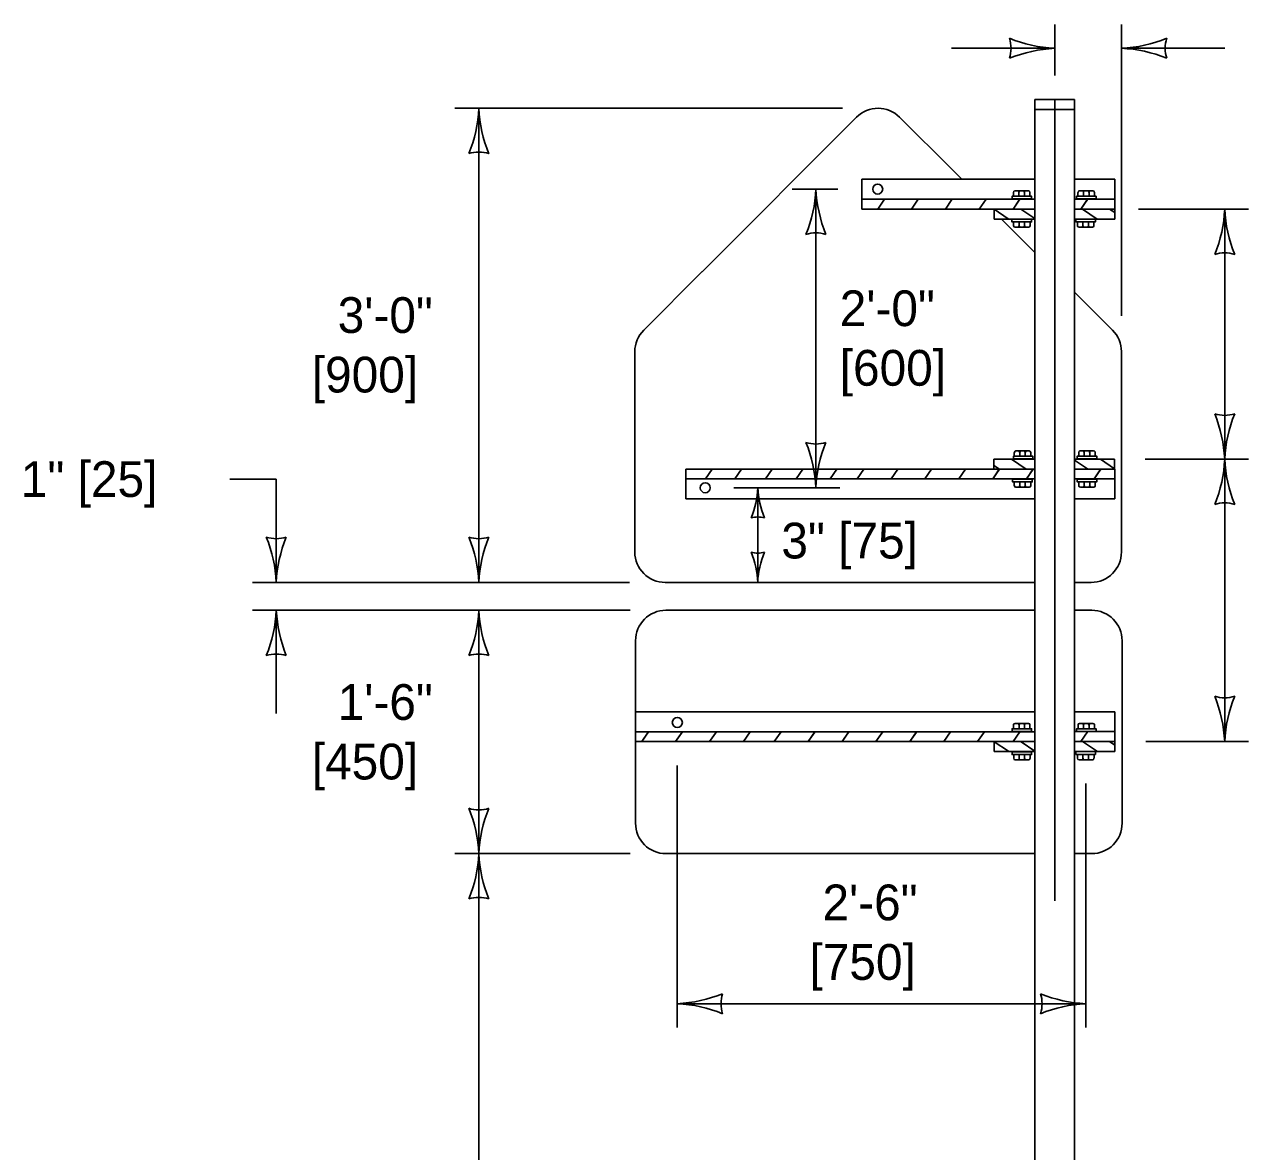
# Model space of a CAD drawing. Extents: x 49991.4 to 50021, y 49987.6 to 50011.4.
# Drawn here: x 50005.155 to 50007.21, y 49995.939 to 49997.831 of the extents above; entities that cross this region are included whole.
import ezdxf

# ---------------------------------------------------------------- set-up
doc = ezdxf.new("R2010")
doc.units = 0
for name, color, linetype in [('Level 1', 7, 'Continuous'), ('Level 2', 7, 'Continuous'), ('Level 3', 7, 'Continuous'), ('Level 4', 7, 'Continuous')]:
    doc.layers.add(name, color=color, linetype=linetype)

msp = doc.modelspace()

# ---------------------------------------------------------------- linework, layer by layer
at = {"layer": 'Level 1'}
for p, q in [((50006.8517, 49997.7052), (50006.9182, 49997.7052)), ((50006.8517, 49997.7052), (50006.8517, 49997.0109)), ((50006.9182, 49997.7052), (50006.9182, 49997.0137)), ((50006.2929, 49997.416), (50006.5522, 49997.6753)), ((50006.6244, 49997.6753), (50006.713, 49997.5868)), ((50006.8517, 49997.6885), (50006.9182, 49997.6885)), ((50006.5609, 49997.5711), (50006.5609, 49997.5211)), ((50006.5609, 49997.5711), (50006.8506, 49997.5711)), ((50006.713, 49997.5868), (50006.7287, 49997.5711)), ((50006.918, 49997.5711), (50006.9857, 49997.5711)), ((50006.9857, 49997.5711), (50006.9857, 49997.5044)), ((50006.8156, 49997.5491), (50006.8156, 49997.5429)), ((50006.8407, 49997.5516), (50006.818, 49997.5516)), ((50006.8408, 49997.5516), (50006.818, 49997.5516)), ((50006.8248, 49997.5516), (50006.8248, 49997.5429)), ((50006.8341, 49997.5516), (50006.8341, 49997.5429)), ((50006.8432, 49997.5491), (50006.8432, 49997.5429)), ((50006.9239, 49997.5491), (50006.9239, 49997.5429)), ((50006.949, 49997.5516), (50006.9264, 49997.5516)), ((50006.9491, 49997.5516), (50006.9264, 49997.5516)), ((50006.9331, 49997.5516), (50006.9331, 49997.5429)), ((50006.9424, 49997.5516), (50006.9424, 49997.5429)), ((50006.9515, 49997.5491), (50006.9515, 49997.5429)), ((50006.5609, 49997.5379), (50006.8512, 49997.5379)), ((50006.5876, 49997.5211), (50006.5989, 49997.5379)), ((50006.6444, 49997.5211), (50006.6557, 49997.5379)), ((50006.7013, 49997.5211), (50006.7122, 49997.5373)), ((50006.7582, 49997.5211), (50006.7695, 49997.5379)), ((50006.815, 49997.5211), (50006.8263, 49997.5379)), ((50006.815, 49997.5211), (50006.8259, 49997.5373)), ((50006.815, 49997.5211), (50006.8259, 49997.5373)), ((50006.815, 49997.5211), (50006.8259, 49997.5373)), ((50006.918, 49997.5379), (50006.9857, 49997.5379)), ((50006.918, 49997.5379), (50006.9857, 49997.5379)), ((50006.9288, 49997.5211), (50006.9401, 49997.5379)), ((50006.9288, 49997.5211), (50006.9397, 49997.5373)), ((50006.5609, 49997.5211), (50006.7831, 49997.5211)), ((50006.7831, 49997.5044), (50006.7831, 49997.5211)), ((50006.7831, 49997.5211), (50006.8512, 49997.5211)), ((50006.8069, 49997.5048), (50006.7831, 49997.5209)), ((50006.8517, 49997.5052), (50006.8281, 49997.5211)), ((50006.918, 49997.5211), (50006.9857, 49997.5211)), ((50006.918, 49997.5211), (50006.9857, 49997.5211)), ((50006.918, 49997.5211), (50006.9857, 49997.5211)), ((50006.9562, 49997.5044), (50006.9315, 49997.5211)), ((50006.9857, 49997.5151), (50006.9767, 49997.5211)), ((50006.7831, 49997.5044), (50006.8517, 49997.5044)), ((50006.7953, 49997.5044), (50006.8517, 49997.4482)), ((50006.8158, 49997.4931), (50006.8158, 49997.4993)), ((50006.8182, 49997.4905), (50006.8409, 49997.4905)), ((50006.8183, 49997.4905), (50006.8409, 49997.4905)), ((50006.8249, 49997.4905), (50006.8249, 49997.4993)), ((50006.8342, 49997.4905), (50006.8342, 49997.4993)), ((50006.8434, 49997.4931), (50006.8434, 49997.4993)), ((50006.9183, 49997.5044), (50006.9857, 49997.5044)), ((50006.923, 49997.4932), (50006.923, 49997.4994)), ((50006.9255, 49997.4906), (50006.9482, 49997.4906)), ((50006.9256, 49997.4906), (50006.9482, 49997.4906)), ((50006.9321, 49997.4906), (50006.9321, 49997.4994)), ((50006.9415, 49997.4906), (50006.9415, 49997.4994)), ((50006.9507, 49997.4932), (50006.9507, 49997.4994)), ((50006.1948, 49997.3179), (50006.2927, 49997.4162)), ((50006.9182, 49997.3815), (50006.932, 49997.3677)), ((50006.932, 49997.3677), (50006.9819, 49997.3179)), ((50006.1798, 49996.9455), (50006.1798, 49997.2818)), ((50006.9968, 49997.2818), (50006.9968, 49996.9455)), ((50006.7828, 49997.1014), (50006.7828, 49997.0847)), ((50006.8517, 49997.1014), (50006.7828, 49997.1014)), ((50006.8124, 49997.1014), (50006.8371, 49997.0847)), ((50006.817, 49997.1126), (50006.817, 49997.1063)), ((50006.8196, 49997.1152), (50006.842, 49997.1152)), ((50006.8196, 49997.1152), (50006.842, 49997.1152)), ((50006.8261, 49997.1152), (50006.8261, 49997.1063)), ((50006.8354, 49997.1152), (50006.8354, 49997.1063)), ((50006.8446, 49997.1126), (50006.8446, 49997.1063)), ((50006.9854, 49997.1014), (50006.9182, 49997.1014)), ((50006.9182, 49997.0998), (50006.9401, 49997.0849)), ((50006.9251, 49997.1127), (50006.9251, 49997.1064)), ((50006.9277, 49997.1153), (50006.9501, 49997.1153)), ((50006.9277, 49997.1153), (50006.9501, 49997.1153)), ((50006.9342, 49997.1153), (50006.9342, 49997.1064)), ((50006.9435, 49997.1153), (50006.9435, 49997.1064)), ((50006.9527, 49997.1127), (50006.9527, 49997.1064)), ((50006.9616, 49997.1011), (50006.9854, 49997.085)), ((50006.9854, 49997.1014), (50006.9854, 49997.085)), ((50006.2655, 49997.0847), (50006.2655, 49997.0347)), ((50006.7828, 49997.0847), (50006.2655, 49997.0847)), ((50006.2985, 49997.068), (50006.3098, 49997.0847)), ((50006.3477, 49997.068), (50006.359, 49997.0847)), ((50006.3993, 49997.068), (50006.4106, 49997.0847)), ((50006.4505, 49997.068), (50006.4619, 49997.0847)), ((50006.5076, 49997.068), (50006.5189, 49997.0847)), ((50006.553, 49997.068), (50006.5642, 49997.0846)), ((50006.61, 49997.068), (50006.6213, 49997.0847)), ((50006.6669, 49997.068), (50006.6781, 49997.0847)), ((50006.7236, 49997.068), (50006.7349, 49997.0847)), ((50006.7807, 49997.068), (50006.7919, 49997.0847)), ((50006.7812, 49997.0687), (50006.7905, 49997.0826)), ((50006.7828, 49997.0908), (50006.7919, 49997.0847)), ((50006.8505, 49997.0847), (50006.7828, 49997.0847)), ((50006.8517, 49997.0847), (50006.7828, 49997.0847)), ((50006.8375, 49997.068), (50006.8487, 49997.0847)), ((50006.838, 49997.0688), (50006.8477, 49997.0832)), ((50006.9857, 49997.0847), (50006.9174, 49997.0847)), ((50006.9857, 49997.0847), (50006.9174, 49997.0847)), ((50006.9857, 49997.0847), (50006.9182, 49997.0847)), ((50006.9513, 49997.0682), (50006.9624, 49997.0847)), ((50006.9513, 49997.0682), (50006.9614, 49997.0832)), ((50006.9857, 49997.0847), (50006.9857, 49997.0347)), ((50006.8517, 49997.068), (50006.2655, 49997.068)), ((50006.817, 49997.0568), (50006.817, 49997.0631)), ((50006.8261, 49997.0542), (50006.8261, 49997.0631)), ((50006.8354, 49997.0542), (50006.8354, 49997.0631)), ((50006.8446, 49997.0568), (50006.8446, 49997.0631)), ((50006.9857, 49997.068), (50006.9174, 49997.068)), ((50006.9857, 49997.068), (50006.9182, 49997.068)), ((50006.9253, 49997.0568), (50006.9253, 49997.0631)), ((50006.9344, 49997.0542), (50006.9344, 49997.0631)), ((50006.9437, 49997.0542), (50006.9437, 49997.0631)), ((50006.9529, 49997.0568), (50006.9529, 49997.0631)), ((50006.8517, 49997.0347), (50006.2655, 49997.0347)), ((50006.8196, 49997.0542), (50006.842, 49997.0542)), ((50006.8196, 49997.0542), (50006.842, 49997.0542)), ((50006.9857, 49997.0347), (50006.9182, 49997.0347)), ((50006.9279, 49997.0542), (50006.9503, 49997.0542)), ((50006.9279, 49997.0542), (50006.9503, 49997.0542)), ((50006.9182, 49997.0137), (50006.9182, 49994.5439)), ((50006.8517, 49997.0109), (50006.8517, 49994.5439)), ((50006.8517, 49996.8944), (50006.2309, 49996.8944)), ((50006.9458, 49996.8944), (50006.9182, 49996.8944)), ((50006.2321, 49996.8476), (50006.8517, 49996.8476)), ((50006.9182, 49996.8476), (50006.9469, 49996.8476)), ((50006.181, 49996.4902), (50006.181, 49996.7965)), ((50006.998, 49996.7965), (50006.998, 49996.4902)), ((50006.1815, 49996.6771), (50006.8513, 49996.6771)), ((50006.9188, 49996.6772), (50006.9858, 49996.6772)), ((50006.9858, 49996.6772), (50006.9858, 49996.6105)), ((50006.181, 49996.6438), (50006.851, 49996.6438)), ((50006.1915, 49996.6271), (50006.2028, 49996.6438)), ((50006.2484, 49996.6271), (50006.2598, 49996.6438)), ((50006.3053, 49996.6271), (50006.3167, 49996.6438)), ((50006.3621, 49996.6271), (50006.3735, 49996.6438)), ((50006.414, 49996.6271), (50006.4253, 49996.6438)), ((50006.4709, 49996.6271), (50006.4822, 49996.6438)), ((50006.5278, 49996.6271), (50006.5392, 49996.6438)), ((50006.5846, 49996.6271), (50006.596, 49996.6438)), ((50006.6415, 49996.6271), (50006.6529, 49996.6438)), ((50006.6984, 49996.6271), (50006.7098, 49996.6438)), ((50006.7554, 49996.6271), (50006.7667, 49996.6438)), ((50006.8151, 49996.6272), (50006.8263, 49996.6438)), ((50006.8157, 49996.6551), (50006.8157, 49996.6489)), ((50006.8408, 49996.6577), (50006.8181, 49996.6577)), ((50006.8408, 49996.6577), (50006.8181, 49996.6577)), ((50006.8249, 49996.6577), (50006.8249, 49996.6489)), ((50006.8342, 49996.6577), (50006.8342, 49996.6489)), ((50006.8433, 49996.6551), (50006.8433, 49996.6489)), ((50006.9181, 49996.6439), (50006.9858, 49996.6439)), ((50006.9182, 49996.6439), (50006.9858, 49996.6439)), ((50006.924, 49996.6551), (50006.924, 49996.6489)), ((50006.9491, 49996.6577), (50006.9264, 49996.6577)), ((50006.9492, 49996.6577), (50006.9264, 49996.6577)), ((50006.9332, 49996.6577), (50006.9332, 49996.6489)), ((50006.9425, 49996.6577), (50006.9425, 49996.6489)), ((50006.9516, 49996.6551), (50006.9516, 49996.6489)), ((50006.181, 49996.6271), (50006.7832, 49996.6271)), ((50006.1915, 49996.6271), (50006.2024, 49996.6432)), ((50006.1915, 49996.6271), (50006.2024, 49996.6432)), ((50006.2484, 49996.6271), (50006.2594, 49996.6432)), ((50006.2484, 49996.6271), (50006.2594, 49996.6432)), ((50006.4709, 49996.6271), (50006.4818, 49996.6432)), ((50006.4709, 49996.6271), (50006.4818, 49996.6432)), ((50006.5277, 49996.6271), (50006.5387, 49996.6432)), ((50006.5278, 49996.6271), (50006.5388, 49996.6432)), ((50006.5278, 49996.6271), (50006.5388, 49996.6432)), ((50006.5846, 49996.6271), (50006.5956, 49996.6432)), ((50006.5846, 49996.6271), (50006.5956, 49996.6432)), ((50006.5847, 49996.6271), (50006.5957, 49996.6432)), ((50006.6415, 49996.6271), (50006.6525, 49996.6432)), ((50006.7832, 49996.6105), (50006.7832, 49996.6271)), ((50006.7832, 49996.6271), (50006.8517, 49996.6271)), ((50006.807, 49996.6109), (50006.7832, 49996.6269)), ((50006.8151, 49996.6272), (50006.826, 49996.6433)), ((50006.8151, 49996.6272), (50006.826, 49996.6433)), ((50006.8151, 49996.6272), (50006.826, 49996.6433)), ((50006.8517, 49996.6112), (50006.8285, 49996.627)), ((50006.9181, 49996.6272), (50006.9858, 49996.6272)), ((50006.9181, 49996.6272), (50006.9858, 49996.6272)), ((50006.9182, 49996.6272), (50006.9858, 49996.6272)), ((50006.9289, 49996.6272), (50006.9398, 49996.6433)), ((50006.9289, 49996.6272), (50006.9398, 49996.6433)), ((50006.9564, 49996.6104), (50006.9317, 49996.6272)), ((50006.9858, 49996.6211), (50006.9767, 49996.6272)), ((50006.7832, 49996.6105), (50006.8517, 49996.6105)), ((50006.8159, 49996.5992), (50006.8159, 49996.6055)), ((50006.825, 49996.5966), (50006.825, 49996.6055)), ((50006.8343, 49996.5966), (50006.8343, 49996.6055)), ((50006.8435, 49996.5992), (50006.8435, 49996.6055)), ((50006.9182, 49996.6105), (50006.9858, 49996.6105)), ((50006.9231, 49996.5993), (50006.9231, 49996.6054)), ((50006.9322, 49996.5967), (50006.9322, 49996.6054)), ((50006.9416, 49996.5967), (50006.9416, 49996.6054)), ((50006.9508, 49996.5993), (50006.9508, 49996.6054)), ((50006.8183, 49996.5966), (50006.841, 49996.5966)), ((50006.8184, 49996.5966), (50006.841, 49996.5966)), ((50006.9256, 49996.5967), (50006.9483, 49996.5967)), ((50006.9257, 49996.5967), (50006.9483, 49996.5967)), ((50006.8517, 49996.4391), (50006.2321, 49996.4391)), ((50006.9469, 49996.4391), (50006.9182, 49996.4391))]:
    msp.add_line(p, q, dxfattribs=at)
for points in [[(50006.846, 49997.5381), (50006.846, 49997.5427), (50006.8131, 49997.5427), (50006.8131, 49997.5381)], [(50006.9543, 49997.5381), (50006.9543, 49997.5427), (50006.9214, 49997.5427), (50006.9214, 49997.5381)], [(50006.813, 49997.5041), (50006.813, 49997.4995), (50006.8459, 49997.4995), (50006.8459, 49997.5041)], [(50006.9203, 49997.5042), (50006.9203, 49997.4996), (50006.9531, 49997.4996), (50006.9531, 49997.5042)], [(50006.8483, 49997.1016), (50006.8483, 49997.1063), (50006.8154, 49997.1063), (50006.8154, 49997.1016)], [(50006.9555, 49997.1017), (50006.9555, 49997.1064), (50006.9226, 49997.1064), (50006.9226, 49997.1017)], [(50006.8142, 49997.0678), (50006.8142, 49997.0631), (50006.8471, 49997.0631), (50006.8471, 49997.0678)], [(50006.9226, 49997.0678), (50006.9226, 49997.0631), (50006.9554, 49997.0631), (50006.9554, 49997.0678)], [(50006.8461, 49996.6441), (50006.8461, 49996.6488), (50006.8132, 49996.6488), (50006.8132, 49996.6441)], [(50006.9544, 49996.6441), (50006.9544, 49996.6488), (50006.9215, 49996.6488), (50006.9215, 49996.6441)], [(50006.8131, 49996.6102), (50006.8131, 49996.6055), (50006.846, 49996.6055), (50006.846, 49996.6102)], [(50006.9204, 49996.6103), (50006.9204, 49996.6056), (50006.9532, 49996.6056), (50006.9532, 49996.6103)]]:
    msp.add_lwpolyline(points, close=True, dxfattribs=at)
for centre in [(50006.5876, 49997.5547), (50006.2981, 49997.0533), (50006.2512, 49996.6593)]:
    msp.add_circle(centre, 0.00843, dxfattribs=at)
for centre, radius, start, end in [((50006.5883, 49997.6392), 0.0511, 45, 135), ((50006.8182, 49997.5491), 0.00257, 90, 180), ((50006.8222, 49997.5491), 0.00257, 0, 90), ((50006.8274, 49997.5491), 0.00257, 90, 180), ((50006.8314, 49997.5491), 0.00257, 0, 90), ((50006.8366, 49997.5491), 0.00257, 90, 180), ((50006.8406, 49997.5491), 0.00257, 0, 90), ((50006.9265, 49997.5491), 0.00257, 90, 180), ((50006.9305, 49997.5491), 0.00257, 0, 90), ((50006.9357, 49997.5491), 0.00257, 90, 180), ((50006.9397, 49997.5491), 0.00257, 0, 90), ((50006.9449, 49997.5491), 0.00257, 90, 180), ((50006.9489, 49997.5491), 0.00257, 0, 90), ((50006.8184, 49997.4931), 0.00257, 180, 270), ((50006.8224, 49997.4931), 0.00257, 270, 0), ((50006.8276, 49997.4931), 0.00257, 180, 270), ((50006.8316, 49997.4931), 0.00257, 270, 0), ((50006.8368, 49997.4931), 0.00257, 180, 270), ((50006.8408, 49997.4931), 0.00257, 270, 0), ((50006.9256, 49997.4932), 0.00257, 180, 270), ((50006.9297, 49997.4932), 0.00257, 270, 0), ((50006.9348, 49997.4932), 0.00257, 180, 270), ((50006.9389, 49997.4932), 0.00257, 270, 0), ((50006.944, 49997.4932), 0.00257, 180, 270), ((50006.9481, 49997.4932), 0.00257, 270, 0), ((50006.2309, 49997.2818), 0.0511, 135, 180), ((50006.9458, 49997.2818), 0.0511, 0, 45), ((50006.8196, 49997.1126), 0.00257, 90, 180), ((50006.8235, 49997.1126), 0.00257, 0, 90), ((50006.8287, 49997.1126), 0.00257, 90, 180), ((50006.8328, 49997.1126), 0.00257, 0, 90), ((50006.838, 49997.1126), 0.00257, 90, 180), ((50006.842, 49997.1126), 0.00257, 0, 90), ((50006.9277, 49997.1127), 0.00257, 90, 180), ((50006.9316, 49997.1127), 0.00257, 0, 90), ((50006.9368, 49997.1127), 0.00257, 90, 180), ((50006.9409, 49997.1127), 0.00257, 0, 90), ((50006.9461, 49997.1127), 0.00257, 90, 180), ((50006.9501, 49997.1127), 0.00257, 0, 90), ((50006.8196, 49997.0568), 0.00257, 180, 270), ((50006.8235, 49997.0568), 0.00257, 270, 0), ((50006.8287, 49997.0568), 0.00257, 180, 270), ((50006.8328, 49997.0568), 0.00257, 270, 0), ((50006.838, 49997.0568), 0.00257, 180, 270), ((50006.842, 49997.0568), 0.00257, 270, 0), ((50006.9279, 49997.0568), 0.00257, 180, 270), ((50006.9318, 49997.0568), 0.00257, 270, 0), ((50006.937, 49997.0568), 0.00257, 180, 270), ((50006.9411, 49997.0568), 0.00257, 270, 0), ((50006.9463, 49997.0568), 0.00257, 180, 270), ((50006.9503, 49997.0568), 0.00257, 270, 0), ((50006.2309, 49996.9455), 0.0511, 180, 270), ((50006.9458, 49996.9455), 0.0511, 270, 0), ((50006.2321, 49996.7965), 0.0511, 90, 180), ((50006.9469, 49996.7965), 0.0511, 0, 90), ((50006.8182, 49996.6551), 0.00257, 90, 180), ((50006.8223, 49996.6551), 0.00257, 0, 90), ((50006.8275, 49996.6551), 0.00257, 90, 180), ((50006.8315, 49996.6551), 0.00257, 0, 90), ((50006.8367, 49996.6551), 0.00257, 90, 180), ((50006.8407, 49996.6551), 0.00257, 0, 90), ((50006.9265, 49996.6551), 0.00257, 90, 180), ((50006.9306, 49996.6551), 0.00257, 0, 90), ((50006.9358, 49996.6551), 0.00257, 90, 180), ((50006.9398, 49996.6551), 0.00257, 0, 90), ((50006.945, 49996.6551), 0.00257, 90, 180), ((50006.949, 49996.6551), 0.00257, 0, 90), ((50006.8185, 49996.5991), 0.00257, 180, 270), ((50006.8225, 49996.5991), 0.00257, 270, 0), ((50006.8277, 49996.5991), 0.00257, 180, 270), ((50006.8317, 49996.5991), 0.00257, 270, 0), ((50006.8369, 49996.5991), 0.00257, 180, 270), ((50006.8409, 49996.5991), 0.00257, 270, 0), ((50006.9257, 49996.5992), 0.00257, 180, 270), ((50006.9298, 49996.5992), 0.00257, 270, 0), ((50006.9349, 49996.5992), 0.00257, 180, 270), ((50006.939, 49996.5992), 0.00257, 270, 0), ((50006.9441, 49996.5992), 0.00257, 180, 270), ((50006.9482, 49996.5992), 0.00257, 270, 0), ((50006.2321, 49996.4902), 0.0511, 180, 270), ((50006.9469, 49996.4902), 0.0511, 270, 0)]:
    msp.add_arc(centre, radius, start, end, dxfattribs=at)
at = {"layer": 'Level 3'}
for p, q in [((50006.8849, 49997.7452), (50006.8849, 49997.831)), ((50006.9968, 49997.4935), (50006.9968, 49997.831)), ((50006.8114, 49997.791), (50006.7114, 49997.791)), ((50006.8114, 49997.791), (50006.8849, 49997.791)), ((50006.9968, 49997.791), (50007.1702, 49997.791)), ((50005.8779, 49997.6903), (50006.5283, 49997.6903)), ((50005.9179, 49996.8944), (50005.9179, 49997.6903)), ((50006.4439, 49997.5546), (50006.5209, 49997.5546)), ((50006.4839, 49997.0533), (50006.4839, 49997.5546)), ((50007.0257, 49997.5211), (50007.2102, 49997.5211)), ((50007.1702, 49997.5211), (50007.1702, 49997.1014)), ((50006.9968, 49997.3418), (50006.9968, 49997.4942)), ((50007.0368, 49997.1014), (50007.2102, 49997.1014)), ((50007.1702, 49996.6272), (50007.1702, 49997.1014)), ((50005.5001, 49997.0678), (50005.5779, 49997.0678)), ((50005.5779, 49996.8944), (50005.5779, 49997.0678)), ((50006.3462, 49997.0533), (50006.5239, 49997.0533)), ((50006.3862, 49996.8944), (50006.3862, 49997.0533)), ((50005.5379, 49996.8944), (50006.1709, 49996.8944)), ((50005.5379, 49996.8476), (50006.1721, 49996.8476)), ((50005.5779, 49996.6742), (50005.5779, 49996.8476)), ((50005.9179, 49996.4391), (50005.9179, 49996.8476)), ((50007.038, 49996.6272), (50007.2102, 49996.6272)), ((50006.2512, 49996.4871), (50006.2512, 49996.5871)), ((50006.937, 49996.1472), (50006.937, 49996.5567)), ((50006.2512, 49996.1472), (50006.2512, 49996.4871)), ((50005.8779, 49996.4391), (50006.1721, 49996.4391)), ((50005.9179, 49994.5439), (50005.9179, 49996.4391)), ((50006.2512, 49996.1872), (50006.937, 49996.1872))]:
    msp.add_line(p, q, dxfattribs=at)
for centre, radius, start, end in [((50006.894, 49998.0131), 0.2223, 247.456, 267.6395), ((50006.7567, 49997.791), 0.0548, 342.1388, 17.8612), ((50006.9853, 49998.0237), 0.233, 272.8273, 292.0772), ((50007.125, 49997.791), 0.0548, 162.1388, 197.8612), ((50006.8964, 49997.5583), 0.233, 92.8273, 112.0772), ((50006.9877, 49997.5689), 0.2223, 67.456, 87.6395), ((50005.6958, 49997.6994), 0.2223, 337.456, 357.6395), ((50006.1506, 49997.7017), 0.233, 182.8273, 202.0772), ((50005.9179, 49997.562), 0.0548, 72.1388, 107.8612), ((50006.2618, 49997.5638), 0.2223, 337.456, 357.6395), ((50006.7166, 49997.5661), 0.233, 182.8273, 202.0772), ((50006.9481, 49997.5303), 0.2223, 337.456, 357.6395), ((50007.4029, 49997.5326), 0.233, 182.8273, 202.0772), ((50006.4839, 49997.4264), 0.0548, 72.1388, 107.8612), ((50007.1702, 49997.3929), 0.0548, 72.1388, 107.8612), ((50007.1702, 49997.2296), 0.0548, 252.1388, 287.8612), ((50006.9375, 49997.0899), 0.233, 2.8273, 22.0772), ((50007.3923, 49997.0922), 0.2223, 157.456, 177.6395), ((50006.4839, 49997.1815), 0.0548, 252.1388, 287.8612), ((50006.2512, 49997.0418), 0.233, 2.8273, 22.0772), ((50006.706, 49997.0441), 0.2223, 157.456, 177.6395), ((50006.9481, 49997.1106), 0.2223, 337.456, 357.6395), ((50007.4029, 49997.1129), 0.233, 182.8273, 202.0772), ((50006.2381, 49997.0594), 0.1482, 337.456, 357.6395), ((50006.5414, 49997.061), 0.1553, 182.8273, 202.0772), ((50007.1702, 49996.9732), 0.0548, 72.1388, 107.8612), ((50006.3862, 49996.9678), 0.0365, 72.1388, 107.8612), ((50005.5779, 49997.0226), 0.0548, 252.1388, 287.8612), ((50005.3452, 49996.8829), 0.233, 2.8273, 22.0772), ((50005.8, 49996.8852), 0.2223, 157.456, 177.6395), ((50005.9179, 49997.0226), 0.0548, 252.1388, 287.8612), ((50005.6852, 49996.8829), 0.233, 2.8273, 22.0772), ((50006.14, 49996.8852), 0.2223, 157.456, 177.6395), ((50006.3862, 49996.9799), 0.0365, 252.1388, 287.8612), ((50006.2311, 49996.8867), 0.1553, 2.8273, 22.0772), ((50006.5343, 49996.8883), 0.1482, 157.456, 177.6395), ((50005.3558, 49996.8568), 0.2223, 337.456, 357.6395), ((50005.8106, 49996.8591), 0.233, 182.8273, 202.0772), ((50005.6958, 49996.8568), 0.2223, 337.456, 357.6395), ((50006.1506, 49996.8591), 0.233, 182.8273, 202.0772), ((50005.5779, 49996.7194), 0.0548, 72.1388, 107.8612), ((50005.9179, 49996.7194), 0.0548, 72.1388, 107.8612), ((50007.1702, 49996.7554), 0.0548, 252.1388, 287.8612), ((50006.9375, 49996.6157), 0.233, 2.8273, 22.0772), ((50007.3923, 49996.618), 0.2223, 157.456, 177.6395), ((50005.9179, 49996.5673), 0.0548, 252.1388, 287.8612), ((50005.6852, 49996.4276), 0.233, 2.8273, 22.0772), ((50006.14, 49996.4299), 0.2223, 157.456, 177.6395), ((50005.6958, 49996.4483), 0.2223, 337.456, 357.6395), ((50006.1506, 49996.4506), 0.233, 182.8273, 202.0772), ((50005.9179, 49996.3109), 0.0548, 72.1388, 107.8612), ((50006.2397, 49996.4199), 0.233, 272.8273, 292.0772), ((50006.3794, 49996.1872), 0.0548, 162.1388, 197.8612), ((50006.9462, 49996.4093), 0.2223, 247.456, 267.6395), ((50006.8088, 49996.1872), 0.0548, 342.1388, 17.8612), ((50006.242, 49995.9651), 0.2223, 67.456, 87.6395), ((50006.9485, 49995.9545), 0.233, 92.8273, 112.0772)]:
    msp.add_arc(centre, radius, start, end, dxfattribs=at)
at = {"layer": 'Level 4'}
msp.add_line((50006.8849, 49997.7052), (50006.8849, 49996.3601), dxfattribs=at)

# ---------------------------------------------------------------- texts
at = {"layer": 'Level 2'}
for s, p in [('2\'-0"', (50006.5239, 49997.3246)), ('3\'-0"', (50005.681, 49997.3132)), ('[600]', (50006.5239, 49997.2246)), ('[900]', (50005.6375, 49997.2132)), ('1" [25]', (50005.149, 49997.0378)), ('3" [75]', (50006.4259, 49996.9346)), ('1\'-6"', (50005.681, 49996.6636)), ('[450]', (50005.6375, 49996.5636)), ('2\'-6"', (50006.4949, 49996.3272)), ('[750]', (50006.4731, 49996.2272))]:
    msp.add_text(s, height=0.06, dxfattribs=at).set_placement(p)

doc.saveas('drawing.dxf')
